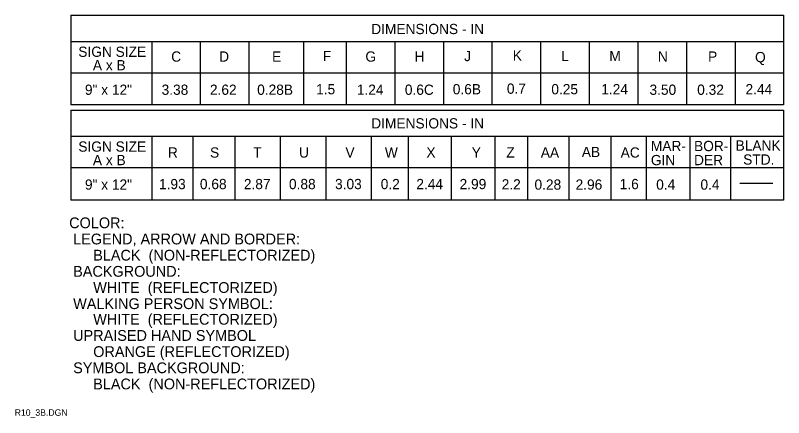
# Model space of a CAD drawing. Extents: x 0.013 to 0.191, y 0.004 to 0.259.
# Drawn here: x 0.0125 to 0.1905, y 0.0038 to 0.0971 of the extents above; entities that cross this region are included whole.
import ezdxf

# ---------------------------------------------------------------- set-up
doc = ezdxf.new("R2010")
doc.units = 0
doc.layers.add('1', color=7, linetype='Continuous')
doc.layers.add('3', color=7, linetype='Continuous')

msp = doc.modelspace()

# ---------------------------------------------------------------- linework, layer by layer
at = {"layer": '3'}
for p, q in [((0.02538, 0.09713), (0.02538, 0.07637)), ((0.02538, 0.09713), (0.1905, 0.09713)), ((0.1905, 0.09713), (0.1905, 0.07637)), ((0.1905, 0.091), (0.02538, 0.091)), ((0.04412, 0.09088), (0.04412, 0.07636)), ((0.05538, 0.09088), (0.05538, 0.07636)), ((0.06664, 0.09088), (0.06664, 0.07636)), ((0.07932, 0.09088), (0.07932, 0.07636)), ((0.08916, 0.09088), (0.08916, 0.07636)), ((0.10042, 0.09088), (0.10042, 0.07636)), ((0.11168, 0.09088), (0.11168, 0.07636)), ((0.12294, 0.09088), (0.12294, 0.07636)), ((0.1342, 0.09088), (0.1342, 0.07636)), ((0.14546, 0.09088), (0.14546, 0.07636)), ((0.15672, 0.09088), (0.15672, 0.07636)), ((0.16798, 0.09088), (0.16798, 0.07636)), ((0.17924, 0.09088), (0.17924, 0.07636)), ((0.1905, 0.08375), (0.02538, 0.08375)), ((0.1905, 0.07637), (0.02538, 0.07637)), ((0.02538, 0.07512), (0.02538, 0.05425)), ((0.02538, 0.07512), (0.1905, 0.07512)), ((0.1905, 0.07512), (0.1905, 0.05425)), ((0.1905, 0.069), (0.02538, 0.069)), ((0.04412, 0.06899), (0.04412, 0.05424)), ((0.05363, 0.06899), (0.05363, 0.05424)), ((0.06336, 0.06899), (0.06336, 0.05424)), ((0.0739, 0.06899), (0.0739, 0.05424)), ((0.08445, 0.06899), (0.08445, 0.05424)), ((0.09499, 0.06899), (0.09499, 0.05424)), ((0.10353, 0.06899), (0.10353, 0.05424)), ((0.11351, 0.06899), (0.11351, 0.05424)), ((0.12362, 0.06899), (0.12362, 0.05424)), ((0.13117, 0.06899), (0.13117, 0.05424)), ((0.14076, 0.06899), (0.14076, 0.05424)), ((0.15051, 0.06899), (0.15051, 0.05424)), ((0.15864, 0.06895), (0.15864, 0.05433)), ((0.16879, 0.06895), (0.16879, 0.05433)), ((0.1782, 0.06895), (0.1782, 0.05433)), ((0.1905, 0.06175), (0.02538, 0.06175)), ((0.188, 0.05813), (0.18038, 0.05813)), ((0.1905, 0.05425), (0.02538, 0.05425))]:
    msp.add_line(p, q, dxfattribs=at)

# ---------------------------------------------------------------- texts
at = {"layer": '1'}
for s, height, p in [('COLOR:', 0.0025, (0.025, 0.04775)), (' LEGEND, ARROW AND BORDER:', 0.0024998, (0.025, 0.044)), ('      BLACK  (NON-REFLECTORIZED)', 0.0024998, (0.025, 0.04025)), (' BACKGROUND:', 0.0024998, (0.025, 0.0365)), ('      WHITE  (REFLECTORIZED)', 0.0024998, (0.025, 0.03275)), (' WALKING PERSON SYMBOL:', 0.0024998, (0.025, 0.029)), ('      WHITE  (REFLECTORIZED)', 0.0024998, (0.025, 0.02538)), (' UPRAISED HAND SYMBOL', 0.0024998, (0.025, 0.02163)), ('      ORANGE (REFLECTORIZED)', 0.0024998, (0.025, 0.01788)), (' SYMBOL BACKGROUND:', 0.0024998, (0.025, 0.01413)), ('      BLACK  (NON-REFLECTORIZED)', 0.0024998, (0.025, 0.01038)), ('R10_3B.DGN', 0.0015, (0.01238, 0.00425))]:
    msp.add_text(s, height=height, dxfattribs=at).set_placement(p)
at = {"layer": '3'}
for s, height, p in [('DIMENSIONS - IN', 0.0023752, (0.09498, 0.09277)), ('SIGN SIZE', 0.002375, (0.02712, 0.0875)), ('K', 0.00238, (0.12775, 0.08663)), ('C', 0.00238, (0.04863, 0.08638)), ('D', 0.00238, (0.05975, 0.08638)), ('E', 0.00238, (0.072, 0.08638)), ('F', 0.00238, (0.08375, 0.0865)), ('G', 0.00238, (0.09362, 0.08638)), ('H', 0.00238, (0.105, 0.08638)), ('J', 0.00238, (0.1165, 0.0865)), ('L', 0.00238, (0.139, 0.0865)), ('M', 0.00238, (0.15013, 0.0865)), ('N', 0.00238, (0.16137, 0.08638)), ('P', 0.00238, (0.173, 0.08638)), ('Q', 0.00238, (0.18388, 0.08625)), ('A x B', 0.002375, (0.0305, 0.08438)), ('9" x 12"', 0.002375, (0.02865, 0.07869)), ('3.38', 0.002375, (0.04642, 0.07869)), ('2.62', 0.002375, (0.05761, 0.07869)), ('0.28B', 0.002375, (0.06855, 0.07869)), ('1.5', 0.002375, (0.08221, 0.07881)), ('1.24', 0.002375, (0.09164, 0.07869)), ('0.6C', 0.002375, (0.10276, 0.07869)), ('0.6B', 0.002375, (0.11386, 0.07881)), ('0.7', 0.002375, (0.1264, 0.07894)), ('0.25', 0.002375, (0.13669, 0.07881)), ('1.24', 0.002375, (0.14826, 0.07881)), ('3.50', 0.002375, (0.15943, 0.07869)), ('0.32', 0.002375, (0.17048, 0.07869)), ('2.44', 0.002375, (0.18167, 0.07881)), ('DIMENSIONS - IN', 0.0023752, (0.09498, 0.07089)), ('SIGN SIZE', 0.002375, (0.02712, 0.0655)), ('MAR-', 0.002375, (0.15975, 0.06563)), ('BOR-', 0.002375, (0.16975, 0.06563)), ('BLANK', 0.002375, (0.17938, 0.06575)), ('R', 0.00238, (0.04788, 0.06413)), ('S', 0.00238, (0.05763, 0.06413)), ('T', 0.00238, (0.06763, 0.06413)), ('U', 0.00238, (0.07825, 0.06413)), ('V', 0.00238, (0.089, 0.06413)), ('W', 0.00238, (0.09813, 0.06413)), ('X', 0.00238, (0.10775, 0.06413)), ('Y', 0.00238, (0.11825, 0.06413)), ('Z', 0.00238, (0.12625, 0.06413)), ('AA', 0.002375, (0.13425, 0.06413)), ('AB', 0.002375, (0.14375, 0.06425)), ('AC', 0.002375, (0.15275, 0.06413)), ('A x B', 0.002375, (0.0305, 0.06237)), ('GIN', 0.002375, (0.15975, 0.06237)), ('DER', 0.002375, (0.16975, 0.06237)), ('STD.', 0.002375, (0.18113, 0.0625)), ('9" x 12"', 0.002375, (0.02865, 0.05669)), ('1.93', 0.002375, (0.04581, 0.05681)), ('0.68', 0.002375, (0.05529, 0.05681)), ('2.87', 0.002375, (0.06547, 0.05681)), ('0.88', 0.002375, (0.07592, 0.05681)), ('3.03', 0.002375, (0.08659, 0.05681)), ('0.2', 0.002375, (0.09717, 0.05681)), ('2.44', 0.002375, (0.10542, 0.05681)), ('2.99', 0.002375, (0.11544, 0.05681)), ('2.2', 0.002375, (0.12519, 0.05674)), ('0.28', 0.002375, (0.13279, 0.05669)), ('2.96', 0.002375, (0.14231, 0.05669)), ('1.6', 0.002375, (0.15253, 0.05681)), ('0.4', 0.002375, (0.16098, 0.05669)), ('0.4', 0.002375, (0.17123, 0.05669))]:
    msp.add_text(s, height=height, dxfattribs=at).set_placement(p)

doc.saveas('drawing.dxf')
